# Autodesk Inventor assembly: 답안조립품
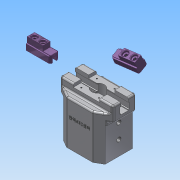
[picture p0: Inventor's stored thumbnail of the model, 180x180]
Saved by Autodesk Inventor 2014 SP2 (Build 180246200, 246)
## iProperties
Created: 2023-05
Part Number: 답안조립품
Document SubType Name: Assembly
Designer: 거성
Author: 거성
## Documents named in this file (8)
- C:\Users\거성\Desktop\730506V1009\답안조립품.iam
- C:\Users\거성\Desktop\730506V1009\본체.ipt
- C:\Users\거성\Desktop\730506V1009\척.ipt
- C:\Users\거성\Desktop\730506V1009\피스톤 로드.ipt
- C:\Users\거성\Desktop\730506V1009\앤드캡.ipt
- C:\Users\거성\Desktop\730506V1009\C형 구멍용 멈춤링 60x2.ipt
- C:\Users\거성\Desktop\730506V1009\O링 P44.ipt
- C:\Users\거성\Desktop\730506V1009\피스톤.ipt
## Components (4 placed, 4 different names)
1. 피스톤 로드:1 — 각도:1
2. C형 구멍용 멈춤링 60x2:1
3. O링 P44:1
4. 피스톤:1
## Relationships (1: Angle 1)
- 각도:1 [Angle]: 피스톤 로드:1
